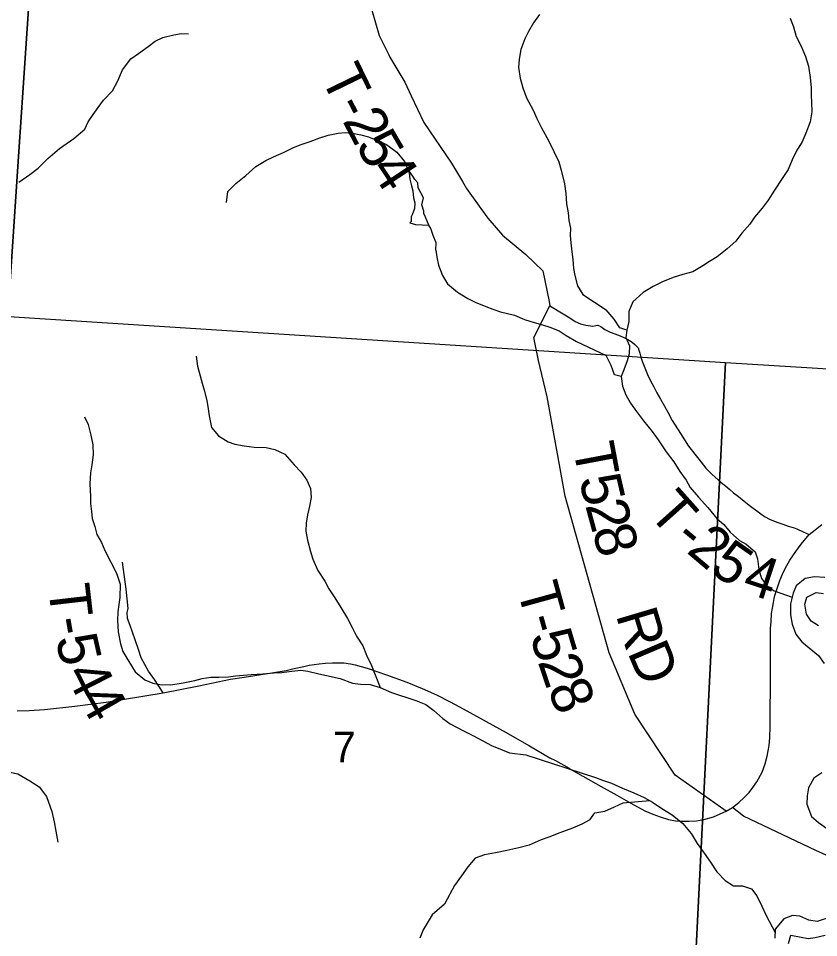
# Model space of a CAD drawing. Extents: x 0 to 34, y 0 to 22.
# Drawn here: x 3.511 to 4.61, y 18.818 to 20.08 of the extents above; entities that cross this region are included whole.
import ezdxf

# ---------------------------------------------------------------- set-up
doc = ezdxf.new("R2010")
doc.units = 0
for name, color, linetype in [('GM_X_Minor_Lake', 7, 'Continuous'), ('GM_X_Minor_River', 7, 'Continuous'), ('GM_X_Section', 7, 'Continuous'), ('GM_X_Section_Text', 7, 'Continuous'), ('GM_X_State_Route', 7, 'Continuous'), ('GM_X_Township_Road', 7, 'Continuous'), ('GM_X_Township_Road_Text', 7, 'Continuous'), ('GM_X_Unincorporated', 7, 'Continuous'), ('SH_Cut_Line', 7, 'Continuous')]:
    doc.layers.add(name, color=color, linetype=linetype)

msp = doc.modelspace()

# ---------------------------------------------------------------- linework, layer by layer
at = {"layer": 'GM_X_Minor_Lake'}
for points in [[(4.0459, 19.873), (4.0474, 19.868), (4.0485, 19.8596), (4.0507, 19.8505), (4.0526, 19.8437), (4.0537, 19.8338), (4.0555, 19.827), (4.0547, 19.8194), (4.0517, 19.8107), (4.0501, 19.8077), (4.0501, 19.8013), (4.0486, 19.7997), (4.0561, 19.7971), (4.0747, 19.7962)], [(4.0747, 19.7962), (4.0698, 19.8072), (4.0679, 19.8125), (4.0676, 19.8156), (4.065, 19.8243), (4.0673, 19.8338), (4.0598, 19.8478), (4.0595, 19.8546), (4.0553, 19.8592), (4.0527, 19.8638), (4.0478, 19.8702), (4.0459, 19.873)]]:
    msp.add_lwpolyline(points, dxfattribs=at)
at = {"layer": 'GM_X_Minor_River'}
for points in [[(4.2267, 20.0858), (4.2185, 20.074), (4.2114, 20.0621), (4.2066, 20.0522), (4.201, 20.0377), (4.1985, 20.0244), (4.1978, 20.013), (4.1999, 19.9982), (4.2038, 19.985), (4.2089, 19.9714), (4.2178, 19.9544), (4.2228, 19.9426), (4.2294, 19.9298), (4.2391, 19.9128), (4.2464, 19.8973), (4.253, 19.8833), (4.2562, 19.872), (4.2609, 19.853), (4.2626, 19.8397), (4.2638, 19.8257), (4.2659, 19.8132), (4.2671, 19.8026), (4.2691, 19.7923), (4.2688, 19.7821), (4.2697, 19.7719), (4.2709, 19.7597), (4.2722, 19.7491), (4.2735, 19.737), (4.2751, 19.7271), (4.279, 19.7131), (4.2863, 19.701), (4.318, 19.6801)], [(4.5709, 20.0804), (4.5754, 20.0686), (4.5791, 20.0556), (4.5859, 20.0419), (4.5922, 20.0278), (4.5959, 20.0145), (4.5985, 19.9989), (4.5999, 19.9848), (4.5998, 19.9749), (4.6002, 19.965), (4.6008, 19.9521), (4.5985, 19.9384), (4.5923, 19.9225), (4.5869, 19.91), (4.5803, 19.8994), (4.5738, 19.8862), (4.568, 19.8729), (4.5599, 19.8604), (4.5495, 19.8442), (4.5407, 19.8309), (4.5323, 19.8196), (4.5219, 19.8075), (4.5154, 19.7977), (4.5047, 19.7852), (4.4962, 19.7746), (4.4844, 19.7637), (4.4706, 19.7531), (4.4603, 19.7464), (4.4508, 19.7404), (4.437, 19.7321), (4.4237, 19.7288), (4.41, 19.7243), (4.3955, 19.7187), (4.3829, 19.7123), (4.3691, 19.7041), (4.355, 19.6913), (4.3492, 19.678), (4.3491, 19.6643), (4.3467, 19.6522), (4.3369, 19.6553), (4.329, 19.6675), (4.318, 19.6801)], [(3.5113, 19.8553), (3.5264, 19.8657), (3.5377, 19.8746), (3.5512, 19.888), (3.5674, 19.9018), (3.587, 19.9153), (3.602, 19.9283), (3.6065, 19.9382), (3.6136, 19.9482), (3.6203, 19.9577), (3.6278, 19.9681), (3.6399, 19.9807), (3.6473, 19.9945), (3.6536, 20.0097), (3.6652, 20.0246), (3.6758, 20.0319), (3.689, 20.0415), (3.6988, 20.0492), (3.7093, 20.0539), (3.7245, 20.0575), (3.7347, 20.0595), (3.7442, 20.0592)], [(3.7966, 19.8277), (3.7984, 19.8425), (3.8096, 19.8536), (3.8232, 19.8644), (3.8371, 19.8771), (3.8507, 19.8852), (3.8613, 19.8902), (3.876, 19.8964), (3.8888, 19.903), (3.8994, 19.9073), (3.9115, 19.9112), (3.9248, 19.9162), (3.9365, 19.9198), (3.9501, 19.9226), (3.9596, 19.9238), (3.9718, 19.9224), (3.9813, 19.9202), (3.9919, 19.9176), (4.0041, 19.9128), (4.0163, 19.9069), (4.0305, 19.8964), (4.0412, 19.8839), (4.0459, 19.873)], [(4.0842, 19.7621), (4.0848, 19.7719), (4.0803, 19.7821), (4.0773, 19.7916), (4.0747, 19.7962)], [(4.0842, 19.7621), (4.0854, 19.7526), (4.0878, 19.7413), (4.0933, 19.7273), (4.1002, 19.7156), (4.114, 19.7043), (4.1281, 19.6957), (4.138, 19.6905), (4.1529, 19.6846), (4.1624, 19.6812), (4.1731, 19.6772), (4.1921, 19.6728), (4.2058, 19.6668), (4.2192, 19.6628), (4.2306, 19.6595), (4.2409, 19.6562), (4.2534, 19.6513), (4.2634, 19.645), (4.2775, 19.6364), (4.318, 19.6174)], [(4.3467, 19.6522), (4.3452, 19.6423), (4.3504, 19.6305), (4.3499, 19.6195), (4.3472, 19.61), (4.3422, 19.5979), (4.3387, 19.5884), (4.3405, 19.5751), (4.3454, 19.5633), (4.3518, 19.5518), (4.3597, 19.5407), (4.3695, 19.5277), (4.3812, 19.5132), (4.3898, 19.5018), (4.4007, 19.485), (4.4113, 19.4716), (4.4192, 19.4582), (4.4282, 19.446), (4.4335, 19.4361), (4.4452, 19.4231), (4.4576, 19.4085), (4.4701, 19.3936), (4.4799, 19.3852), (4.4886, 19.3749), (4.5011, 19.3634), (4.5105, 19.3584), (4.523, 19.348), (4.526, 19.3381), (4.5278, 19.3237), (4.5315, 19.3111), (4.5387, 19.3015), (4.5489, 19.2943), (4.5736, 19.2854)], [(3.755, 19.6166), (3.7567, 19.6029), (3.7606, 19.5893), (3.763, 19.5795), (3.7658, 19.5696), (3.7697, 19.5556), (3.7713, 19.5442), (3.7726, 19.5344), (3.7758, 19.5185), (3.7857, 19.5072), (3.7987, 19.4989), (3.8082, 19.4956), (3.8208, 19.4935), (3.8345, 19.4917), (3.8512, 19.4911), (3.863, 19.4885), (3.8767, 19.4818), (3.8897, 19.4675), (3.899, 19.4574), (3.907, 19.4464), (3.9121, 19.4347), (3.913, 19.4226), (3.9108, 19.4104), (3.9079, 19.3986), (3.9061, 19.3872), (3.9058, 19.3762), (3.9079, 19.3637), (3.9118, 19.3482), (3.9153, 19.3379), (3.9223, 19.3224), (3.9316, 19.3077), (3.9374, 19.2972), (3.9454, 19.2847), (3.9539, 19.2715), (3.9628, 19.2564), (3.9694, 19.2439), (3.9752, 19.2322), (3.9841, 19.2186), (3.9891, 19.2058), (3.9957, 19.1918), (4.0078, 19.1615)], [(4.3387, 19.5884), (4.3296, 19.5907), (4.3251, 19.6037), (4.318, 19.6174)], [(3.6014, 19.5331), (3.6064, 19.5225), (3.6104, 19.5081), (3.6132, 19.4949), (3.6133, 19.4808), (3.6115, 19.4672), (3.6098, 19.4561), (3.6091, 19.4413), (3.6097, 19.4239), (3.6098, 19.4144), (3.611, 19.403), (3.6123, 19.3935), (3.6158, 19.3825), (3.6186, 19.3716), (3.6247, 19.3606), (3.6294, 19.3496), (3.6456, 19.3187), (3.6504, 19.3035), (3.6502, 19.2849), (3.6487, 19.2754), (3.6473, 19.2655), (3.6467, 19.2534), (3.6476, 19.2382), (3.6508, 19.2215), (3.6543, 19.2109), (3.6624, 19.1973), (3.6713, 19.183), (3.6843, 19.1721), (3.6953, 19.1677), (3.7052, 19.1655), (3.72, 19.1652), (3.7371, 19.1681), (3.753, 19.1713), (3.7632, 19.174), (3.775, 19.1756), (3.786, 19.1757), (3.7993, 19.1763), (3.8091, 19.1775), (3.8201, 19.1787), (3.8303, 19.1796), (3.8467, 19.1805), (3.8618, 19.1818), (3.8728, 19.1823), (3.8865, 19.1839), (3.8986, 19.1852), (3.9085, 19.1838), (3.9233, 19.1801), (3.934, 19.1779), (3.9526, 19.1739), (3.9698, 19.1676), (3.9808, 19.1662), (3.9941, 19.1656), (4.0078, 19.1615), (4.0234, 19.1549), (4.0329, 19.1515), (4.0459, 19.1475), (4.0569, 19.1438), (4.0706, 19.1382), (4.0813, 19.13), (4.0936, 19.1191), (4.1039, 19.1116), (4.1222, 19.1019), (4.136, 19.0952), (4.1486, 19.0881), (4.1608, 19.0821), (4.1752, 19.0758), (4.1852, 19.0717), (4.208, 19.069), (4.3035, 19.038)], [(4.6185, 19.3125), (4.6044, 19.3133), (4.5915, 19.311), (4.5793, 19.3012), (4.5751, 19.2913), (4.5713, 19.2765), (4.5713, 19.2613), (4.5736, 19.2483), (4.5789, 19.2346), (4.5869, 19.2244), (4.5971, 19.216), (4.6097, 19.2057), (4.6176, 19.1943)], [(4.61, 19.2463), (4.5998, 19.2528), (4.5933, 19.2623), (4.591, 19.2759), (4.5937, 19.2854), (4.6066, 19.2919), (4.6165, 19.2908)], [(3.463, 19.0629), (3.4767, 19.0528), (3.4893, 19.0476), (3.4988, 19.0451), (3.5102, 19.0429), (3.5263, 19.0332), (3.5392, 19.0253), (3.5493, 19.0118), (3.5567, 18.9913), (3.5598, 18.9773), (3.5622, 18.9644), (3.5651, 18.9493)], [(4.3035, 19.038), (4.3129, 19.0345), (4.3254, 19.0302), (4.3406, 19.0233), (4.3562, 19.0171), (4.3702, 19.0105), (4.3819, 19.004), (4.3948, 18.9955), (4.4088, 18.9867), (4.4235, 18.9748), (4.4349, 18.961), (4.4431, 18.9473), (4.4529, 18.9343), (4.4616, 18.9217), (4.4703, 18.9083), (4.4816, 18.8965), (4.4933, 18.8892), (4.5055, 18.8891), (4.5176, 18.8852), (4.5252, 18.8756), (4.5319, 18.8611), (4.5379, 18.8486), (4.5502, 18.825)], [(4.6145, 19.0442), (4.6035, 19.037), (4.5959, 19.024), (4.5943, 19.013), (4.5939, 19.0012), (4.6, 18.9845), (4.6099, 18.9761), (4.6224, 18.9674)], [(4.2958, 18.9798), (4.3027, 18.9893), (4.3164, 18.9919), (4.3298, 18.9975), (4.3416, 19.0031), (4.378, 19.0062)], [(4.2958, 18.9798), (4.2848, 18.974), (4.272, 18.9686), (4.2546, 18.9619), (4.2394, 18.9561), (4.2288, 18.9522), (4.2126, 18.9452), (4.1982, 18.9413), (4.1815, 18.9377), (4.166, 18.9345), (4.1509, 18.9317), (4.138, 18.9274), (4.1283, 18.9152), (4.1196, 18.9029), (4.1099, 18.8896), (4.1036, 18.8777), (4.0961, 18.864), (4.0792, 18.8494), (4.0669, 18.8288), (4.0624, 18.8174)], [(4.6669, 18.9445), (4.6767, 18.9312), (4.6817, 18.9198), (4.6847, 18.9099), (4.6885, 18.8974), (4.6881, 18.886), (4.6824, 18.8727), (4.6721, 18.8681), (4.6607, 18.8666), (4.6501, 18.8624), (4.6406, 18.8552), (4.6307, 18.8495), (4.6204, 18.8442), (4.6079, 18.8404), (4.5965, 18.8423), (4.5843, 18.8477), (4.5741, 18.8484), (4.5623, 18.8439), (4.5505, 18.8298), (4.5497, 18.8173)], [(4.5687, 18.8099), (4.5717, 18.8213), (4.5858, 18.8187), (4.5957, 18.8171), (4.6052, 18.8183), (4.6189, 18.8213)]]:
    msp.add_lwpolyline(points, dxfattribs=at)
at = {"layer": 'GM_X_Section'}
for points in [[(3.4977, 19.6708), (4.4823, 19.6076), (4.4314, 18.5943), (3.4282, 18.6383)], [(4.4823, 19.6076), (5.5089, 19.5445), (5.4469, 18.529), (4.4314, 18.5943)]]:
    msp.add_lwpolyline(points, close=True, dxfattribs=at)
at = {"layer": 'GM_X_State_Route'}
for points in [[(4.5972, 19.3714), (4.6054, 19.3779), (4.6142, 19.3853)], [(4.5491, 19.2837), (4.55, 19.2879), (4.5533, 19.2989), (4.5566, 19.3086), (4.5604, 19.317), (4.5639, 19.3251), (4.5704, 19.3363), (4.5787, 19.3482), (4.586, 19.3582), (4.5972, 19.3714)], [(4.4829, 18.9918), (4.4917, 18.997), (4.5005, 19.0035), (4.5078, 19.0103), (4.5145, 19.0176), (4.5196, 19.0241), (4.5252, 19.0319), (4.5323, 19.0451), (4.5366, 19.0566), (4.5394, 19.0674), (4.542, 19.0818), (4.5428, 19.0924), (4.5433, 19.108), (4.5437, 19.1836), (4.5441, 19.2428), (4.5447, 19.2518), (4.5453, 19.2633), (4.5465, 19.2706), (4.5479, 19.2784), (4.5491, 19.2837)], [(3.5091, 19.1296), (3.5256, 19.1302), (3.5467, 19.1314), (3.5884, 19.1359), (3.6313, 19.1415), (3.7094, 19.1543), (3.7586, 19.164), (3.8023, 19.1729), (3.8207, 19.1758), (3.859, 19.1818), (3.8788, 19.185), (3.8898, 19.1877), (3.9028, 19.1905), (3.9101, 19.192), (3.9237, 19.1939), (3.9327, 19.1948), (3.9421, 19.1955), (3.9504, 19.1954), (3.9576, 19.1952), (3.9668, 19.1939), (3.9733, 19.1926), (3.9897, 19.1879), (4.0164, 19.1791), (4.0444, 19.1687), (4.0652, 19.1602), (4.085, 19.1516), (4.104, 19.1421), (4.1218, 19.1324), (4.1808, 19.0996), (4.2053, 19.0856)], [(4.2053, 19.0856), (4.2129, 19.0813), (4.241, 19.0652), (4.2485, 19.0613), (4.2672, 19.0506), (4.2684, 19.0498), (4.3112, 19.0257), (4.3327, 19.0135), (4.3521, 19.0027), (4.3715, 18.9923), (4.3822, 18.9876), (4.3925, 18.9838), (4.4037, 18.9805), (4.4135, 18.9786), (4.4221, 18.978), (4.4319, 18.9778), (4.4423, 18.9785), (4.4523, 18.9804), (4.4656, 18.9842), (4.4746, 18.9879), (4.4829, 18.9918)], [(4.7898, 18.8008), (4.7787, 18.8214), (4.766, 18.841), (4.7546, 18.854), (4.7514, 18.8574), (4.7525, 18.8584), (4.7475, 18.8633), (4.7401, 18.87), (4.7339, 18.8754), (4.7189, 18.8856), (4.7118, 18.8898), (4.7035, 18.8943), (4.7029, 18.8934), (4.6864, 18.9017), (4.6064, 18.9377), (4.5069, 18.9849), (4.4917, 18.997)]]:
    msp.add_lwpolyline(points, dxfattribs=at)
at = {"layer": 'GM_X_Township_Road'}
for points in [[(3.9147, 20.2291), (3.9151, 20.2202), (3.9228, 20.1859), (3.9354, 20.1559), (3.9512, 20.1337), (3.967, 20.1214), (3.9854, 20.1069), (3.9963, 20.0916), (4.0065, 20.0569), (4.0146, 20.0404), (4.0196, 20.03)], [(4.0196, 20.03), (4.0211, 20.0269), (4.0416, 19.9926), (4.0504, 19.974), (4.0678, 19.9372), (4.1058, 19.8817), (4.1206, 19.8563), (4.1262, 19.8467), (4.1459, 19.8191)], [(4.1459, 19.8191), (4.1554, 19.8058), (4.1756, 19.7828), (4.2079, 19.7562), (4.2313, 19.7336), (4.2397, 19.6915)], [(4.2397, 19.6915), (4.2409, 19.6855), (4.2462, 19.6824), (4.2546, 19.6772), (4.2683, 19.6691), (4.2757, 19.6643), (4.2828, 19.661), (4.2903, 19.6589), (4.2999, 19.6578), (4.3038, 19.6584), (4.3067, 19.6589), (4.3108, 19.6572), (4.3163, 19.6533), (4.3237, 19.6496), (4.3351, 19.6453), (4.3413, 19.6427), (4.3481, 19.6392), (4.3504, 19.6378), (4.3537, 19.6356), (4.3576, 19.6326), (4.3599, 19.6304), (4.3619, 19.6279), (4.3632, 19.6249), (4.3643, 19.6207), (4.3659, 19.6151), (4.3675, 19.6094), (4.3704, 19.6028), (4.3721, 19.5982), (4.375, 19.5914), (4.3795, 19.5819), (4.3837, 19.5743), (4.3879, 19.5663), (4.3928, 19.5573), (4.3983, 19.5477), (4.4027, 19.5396), (4.4088, 19.5282), (4.4202, 19.5102), (4.4314, 19.4929), (4.4456, 19.475), (4.4551, 19.4625), (4.4634, 19.4544)], [(4.4829, 18.9918), (4.4128, 19.0411), (4.3577, 19.1251), (4.3223, 19.209), (4.2619, 19.4241), (4.237, 19.5606), (4.2252, 19.6104), (4.2186, 19.6419), (4.2409, 19.6855)], [(4.4634, 19.4544), (4.4639, 19.4539), (4.4755, 19.4436), (4.4825, 19.4379), (4.4879, 19.4335), (4.4933, 19.4289), (4.4999, 19.4238), (4.5078, 19.4172), (4.5162, 19.4107), (4.525, 19.404), (4.5326, 19.3987), (4.5368, 19.3957), (4.5425, 19.3928), (4.5481, 19.3902), (4.5538, 19.3882), (4.5607, 19.3858), (4.5683, 19.3832), (4.5751, 19.3811), (4.5801, 19.3792), (4.5889, 19.3755), (4.5972, 19.3714)], [(4.5972, 19.3714), (4.6054, 19.3779), (4.6142, 19.3853)], [(3.7094, 19.1543), (3.6977, 19.1724), (3.6894, 19.184), (3.6793, 19.2023), (3.6759, 19.2137), (3.6676, 19.2374), (3.6642, 19.2469), (3.6608, 19.2563), (3.66, 19.2646), (3.6617, 19.27), (3.6588, 19.2966), (3.6537, 19.3336)]]:
    msp.add_lwpolyline(points, dxfattribs=at)
at = {"layer": 'GM_X_Unincorporated'}
msp.add_lwpolyline([(6.769, 20.9), (2.2853, 20.9), (2.418, 20.5866), (2.7473, 19.8121), (2.9553, 19.318), (2.9956, 19.2227), (3.0781, 19.0279), (3.1249, 18.9173), (3.4011, 18.2653), (3.4595, 19.1305), (3.4599, 19.1361), (3.5099, 19.8769), (3.5456, 20.4047), (3.5457, 20.4056), (3.5462, 20.4144), (3.5651, 20.6937), (3.8602, 20.6728), (4.3099, 20.6409), (6.6484, 20.4847), (6.6568, 20.5136)], close=True, dxfattribs=at)
msp.add_lwpolyline([(8.9, 14.2264), (8.9, 20.3234), (8.6245, 20.3436), (7.6038, 20.4229), (7.3955, 20.4364), (6.962, 20.4644), (6.8381, 20.4724), (6.7584, 20.4776), (6.6718, 20.4832), (6.6484, 20.4847), (4.3099, 20.6409), (3.8602, 20.6728), (3.5651, 20.6937), (3.5462, 20.4144), (3.5457, 20.4056), (3.5456, 20.4047), (3.5099, 19.8769)], dxfattribs=at)
at = {"layer": 'SH_Cut_Line'}
for points in [[(4.2937, 16.1161), (4.0882, 16.6114), (3.972, 16.8916), (3.7367, 17.4136), (3.709, 17.484), (3.4011, 18.2653), (3.4595, 19.1305), (3.4599, 19.1361), (3.5099, 19.8769), (3.5456, 20.4047), (3.5457, 20.4056), (3.5462, 20.4144), (3.5651, 20.6937), (3.8602, 20.6728), (4.3099, 20.6409), (6.6484, 20.4847), (6.6568, 20.5136), (6.769, 20.9), (2.1, 20.9), (2.1, 14.1)], [(8.9, 14.1), (8.9, 20.9), (6.769, 20.9), (6.6568, 20.5136), (6.6484, 20.4847), (4.3099, 20.6409), (3.8602, 20.6728), (3.5651, 20.6937), (3.5462, 20.4144), (3.5457, 20.4056), (3.5456, 20.4047), (3.5099, 19.8769), (3.4599, 19.1361), (3.4595, 19.1305), (3.4011, 18.2653), (3.709, 17.484), (3.7367, 17.4136), (3.972, 16.8916), (4.0882, 16.6114), (4.2937, 16.1161)]]:
    msp.add_lwpolyline(points, dxfattribs=at)

# ---------------------------------------------------------------- texts
at = {"layer": 'GM_X_Section_Text'}
msp.add_text('7', height=0.0419, rotation=0, dxfattribs=at).set_placement((3.9429, 19.0589))
at = {"layer": 'GM_X_Township_Road_Text'}
for s, rotation, p in [('T', 295.8962, (3.9253, 20.0003)), ('-', 297.3992, (3.9446, 19.9606)), ('2', 297.627, (3.9554, 19.9397)), ('5', 300.2666, (3.973, 19.9062)), ('4', 303.3891, (3.9925, 19.8731)), ('T', 280.6686, (4.2722, 19.4926)), ('5', 283.0271, (4.2806, 19.4483)), ('T', 311.7602, (4.3742, 19.4007)), ('2', 285.1778, (4.2891, 19.412)), ('8', 285.793, (4.2984, 19.3776)), ('-', 320.4125, (4.4092, 19.3625)), ('2', 319.804, (4.4271, 19.3477)), ('5', 325.0392, (4.4583, 19.3217)), ('4', 341.7068, (4.503, 19.2936)), ('T', 285.4209, (4.1953, 19.2975)), ('T', 276.6102, (3.5515, 19.3008)), ('R', 286.5802, (4.3311, 19.2614)), ('-', 279.9174, (3.5569, 19.2551)), ('-', 285.6819, (4.2067, 19.2563)), ('5', 282.7578, (3.5615, 19.2291)), ('5', 286.5848, (4.2133, 19.2329)), ('D', 293.0641, (4.3468, 19.2102)), ('2', 288.55, (4.2239, 19.1973)), ('4', 296.8618, (3.5744, 19.1806)), ('8', 292.9138, (4.2367, 19.1597)), ('4', 299.8129, (3.5917, 19.1466))]:
    msp.add_text(s, height=0.0568, rotation=rotation, dxfattribs=at).set_placement(p)

doc.saveas('drawing.dxf')
